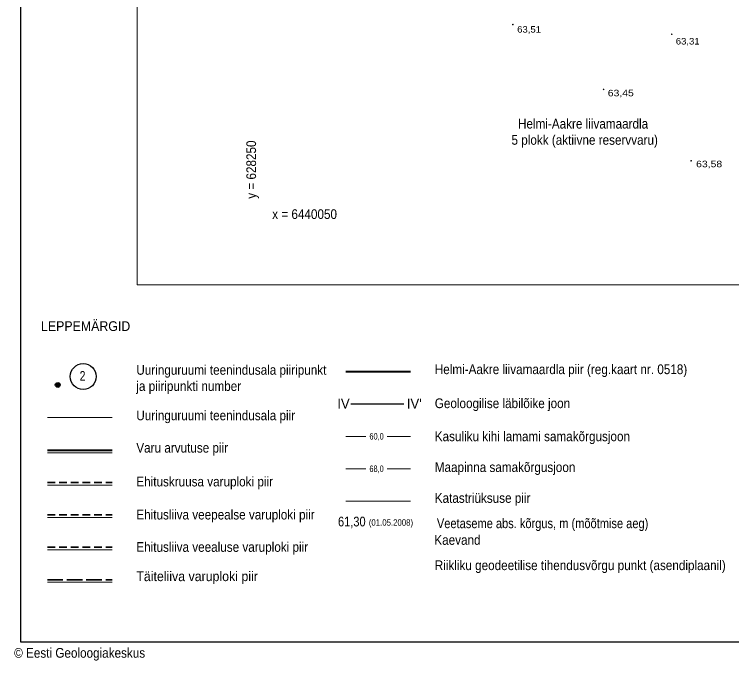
# Model space of a CAD drawing. Extents: x 628176 to 629009, y 6439913 to 6440496.
# Drawn here: x 628176.3 to 628397.5, y 6439912.8 to 6440112.2 of the extents above; entities that cross this region are included whole.
import ezdxf
from ezdxf.enums import TextEntityAlignment as Align

# ---------------------------------------------------------------- set-up
doc = ezdxf.new("R2010")
doc.units = 0
doc.header["$LTSCALE"] = 0.8
doc.linetypes.add('LONG_DASHED', pattern=[7.5, 6, -1.5])
doc.linetypes.add('MEDIUM_DASHED', pattern=[4.5, 3, -1.5])
for name, color, linetype, lineweight in [('1', 7, 'Continuous', 13), ('12', 7, 'Continuous', 13), ('50', 7, 'Continuous', 13)]:
    doc.layers.add(name, color=color, linetype=linetype, lineweight=lineweight)
doc.layers.add('4', color=7, linetype='Continuous')

msp = doc.modelspace()

# ---------------------------------------------------------------- hatches: boundary and pattern name
at = {"layer": '1'}
for points in [[(628330.0999, 6440108.9999, 1), (628329.8999, 6440108.9999, 1)], [(628379.0999, 6440105.9999, 1), (628378.8999, 6440105.9999, 1)], [(628358.0999, 6440088.9999, 1), (628357.8999, 6440088.9999, 1)], [(628385.0999, 6440066.9999, 1), (628384.8999, 6440066.9999, 1)]]:
    msp.add_hatch(color=256, dxfattribs=at).paths.add_polyline_path(points)
at = {"layer": '50'}
msp.add_hatch(color=256, dxfattribs=at).paths.add_polyline_path([(628190.4111, 6439997.8236, 1), (628188.9111, 6439997.8236, 1)])

# ---------------------------------------------------------------- linework, layer by layer
at = {"layer": '1'}
for centre in [(628329.9999, 6440108.9999), (628378.9999, 6440105.9999), (628357.9999, 6440088.9999), (628384.9999, 6440066.9999)]:
    msp.add_circle(centre, 0.1, dxfattribs=at)
at = {"layer": '50', "lineweight": 40}
for p, q in [((628278.46, 6440001.97), (628298.46, 6440001.97)), ((628186.48, 6439977.73), (628206.48, 6439977.73))]:
    msp.add_line(p, q, dxfattribs=at)
at = {"layer": '50', "lineweight": 25}
msp.add_line((628280.05, 6439991.97), (628296.35, 6439991.97), dxfattribs=at)
at = {"layer": '50'}
for p, q in [((628186.48, 6439987.73), (628206.48, 6439987.73)), ((628278.46, 6439981.97), (628284.71, 6439981.97)), ((628291.26, 6439981.97), (628298.46, 6439981.97)), ((628186.48, 6439976.93), (628206.48, 6439976.93)), ((628278.46, 6439971.97), (628284.71, 6439971.97)), ((628291.26, 6439971.97), (628298.46, 6439971.97)), ((628186.48, 6439966.93), (628206.48, 6439966.93)), ((628278.46, 6439961.97), (628298.46, 6439961.97)), ((628186.48, 6439956.93), (628206.48, 6439956.93)), ((628186.48, 6439946.93), (628206.48, 6439946.93)), ((628186.48, 6439936.93), (628206.48, 6439936.93))]:
    msp.add_line(p, q, dxfattribs=at)
at = {"layer": '50', "linetype": 'MEDIUM_DASHED', "lineweight": 35}
for p, q in [((628186.48, 6439967.73), (628206.48, 6439967.73)), ((628186.48, 6439957.73), (628206.48, 6439957.73)), ((628186.48, 6439947.73), (628206.48, 6439947.73))]:
    msp.add_line(p, q, dxfattribs=at)
at = {"layer": '50', "linetype": 'LONG_DASHED', "lineweight": 35}
msp.add_line((628186.48, 6439937.73), (628206.48, 6439937.73), dxfattribs=at)
at = {"layer": '50', "lineweight": 25}
msp.add_lwpolyline([(628178.27, 6440495.9), (629008.51, 6440495.9), (629008.51, 6439918.47), (628178.27, 6439918.47)], close=True, dxfattribs=at)
at = {"layer": '50'}
msp.add_lwpolyline([(628214.18, 6440472.45), (628760.23, 6440472.45), (628760.23, 6440028.67), (628214.18, 6440028.67)], close=True, dxfattribs=at)
at = {"layer": '50', "lineweight": 25}
for centre, radius in [((628197.5162, 6440000.417), 4), ((628189.6611, 6439997.8236), 0.75)]:
    msp.add_circle(centre, radius, dxfattribs=at)

# ---------------------------------------------------------------- texts
at = {"layer": '1'}
for s, width, p in [('63,51', 1.1, (628331.33, 6440106.51)), ('63,31', 1.1, (628380.24, 6440102.85)), ('63,45', 1.2, (628359.28, 6440086.88)), ('63,58', 1.2, (628386.52, 6440064.99))]:
    msp.add_text(s, height=2, dxfattribs=dict(at, width=width)).set_placement(p)
at = {"layer": '12'}
for s, height, width, p in [('61,30', 3, 0.85, (628280.34, 6439954.18)), ('(01.05.2008)', 2, 0.9, (628292.415, 6439954.39))]:
    msp.add_text(s, height=height, dxfattribs=dict(at, width=width)).set_placement(p, align=Align.CENTER)
at = {"layer": '4', "width": 0.9}
msp.add_text('y = 628250', height=3, rotation=90, dxfattribs=at).set_placement((628250.82, 6440055.27))
msp.add_text('x = 6440050', height=3, dxfattribs=at).set_placement((628255.8, 6440049.02))
at = {"layer": '50'}
for s, height, width, p in [('Helmi-Aakre liivamaardla ', 3, 0.9, (628352.165, 6440076.92)), ('5 plokk (aktiivne reservvaru)', 3, 0.9, (628352.16, 6440071.92)), ('LEPPEMÄRGID', 3, 0.95, (628198.265, 6440014.47)), ('2', 3, 0.8, (628197.315, 6439999.1)), ('60,0', 2, 0.85, (628287.985, 6439980.97)), ('68,0', 2, 0.85, (628287.985, 6439970.97)), ('Veetaseme abs. kõrgus, m (mõõtmise aeg)', 3, 0.85, (628339.18, 6439953.64)), ('Kaevand', 3, 0.9, (628312.915, 6439948.51))]:
    msp.add_text(s, height=height, dxfattribs=dict(at, width=width)).set_placement(p, align=Align.CENTER)
for s, width, p in [('Uuringuruumi teenindusala piiripunkt ', 0.9, (628213.9, 6440000.97)), ('Helmi-Aakre liivamaardla piir (reg.kaart nr. 0518)', 0.9, (628305.93, 6440001.16)), ('ja piiripunkti number', 0.9, (628213.9, 6439995.97)), ('Geoloogilise läbilõike joon', 0.9, (628305.93, 6439990.67)), ('Uuringuruumi teenindusala piir', 0.9, (628213.9, 6439986.93)), ('Kasuliku kihi lamami samakõrgusjoon', 0.9, (628305.93, 6439980.47)), ('Varu arvutuse piir', 0.9, (628213.9, 6439976.95)), ('Maapinna samakõrgusjoon', 0.9, (628305.93, 6439970.96)), ('Ehituskruusa varuploki piir', 0.9, (628213.9, 6439966.52)), ('Katastriüksuse piir', 0.9, (628305.93, 6439961.45)), ('Ehitusliiva veepealse varuploki piir', 0.9, (628213.9, 6439956.32)), ('Ehitusliiva veealuse varuploki piir', 0.9, (628213.9, 6439946.34)), ('Riikliku geodeetilise tihendusvõrgu punkt (asendiplaanil)', 0.9, (628305.93, 6439940.7)), ('Täiteliiva varuploki piir', 0.95, (628213.9, 6439937.3)), ('© Eesti Geoloogiakeskus', 0.9, (628176.23, 6439913.67))]:
    msp.add_text(s, height=3, dxfattribs=dict(at, width=width)).set_placement(p)
for s, p in [('IV', (628277.78, 6439990.54)), ("IV'", (628299.61, 6439990.54))]:
    msp.add_text(s, height=3, dxfattribs=at).set_placement(p, align=Align.CENTER)

doc.saveas('drawing.dxf')
